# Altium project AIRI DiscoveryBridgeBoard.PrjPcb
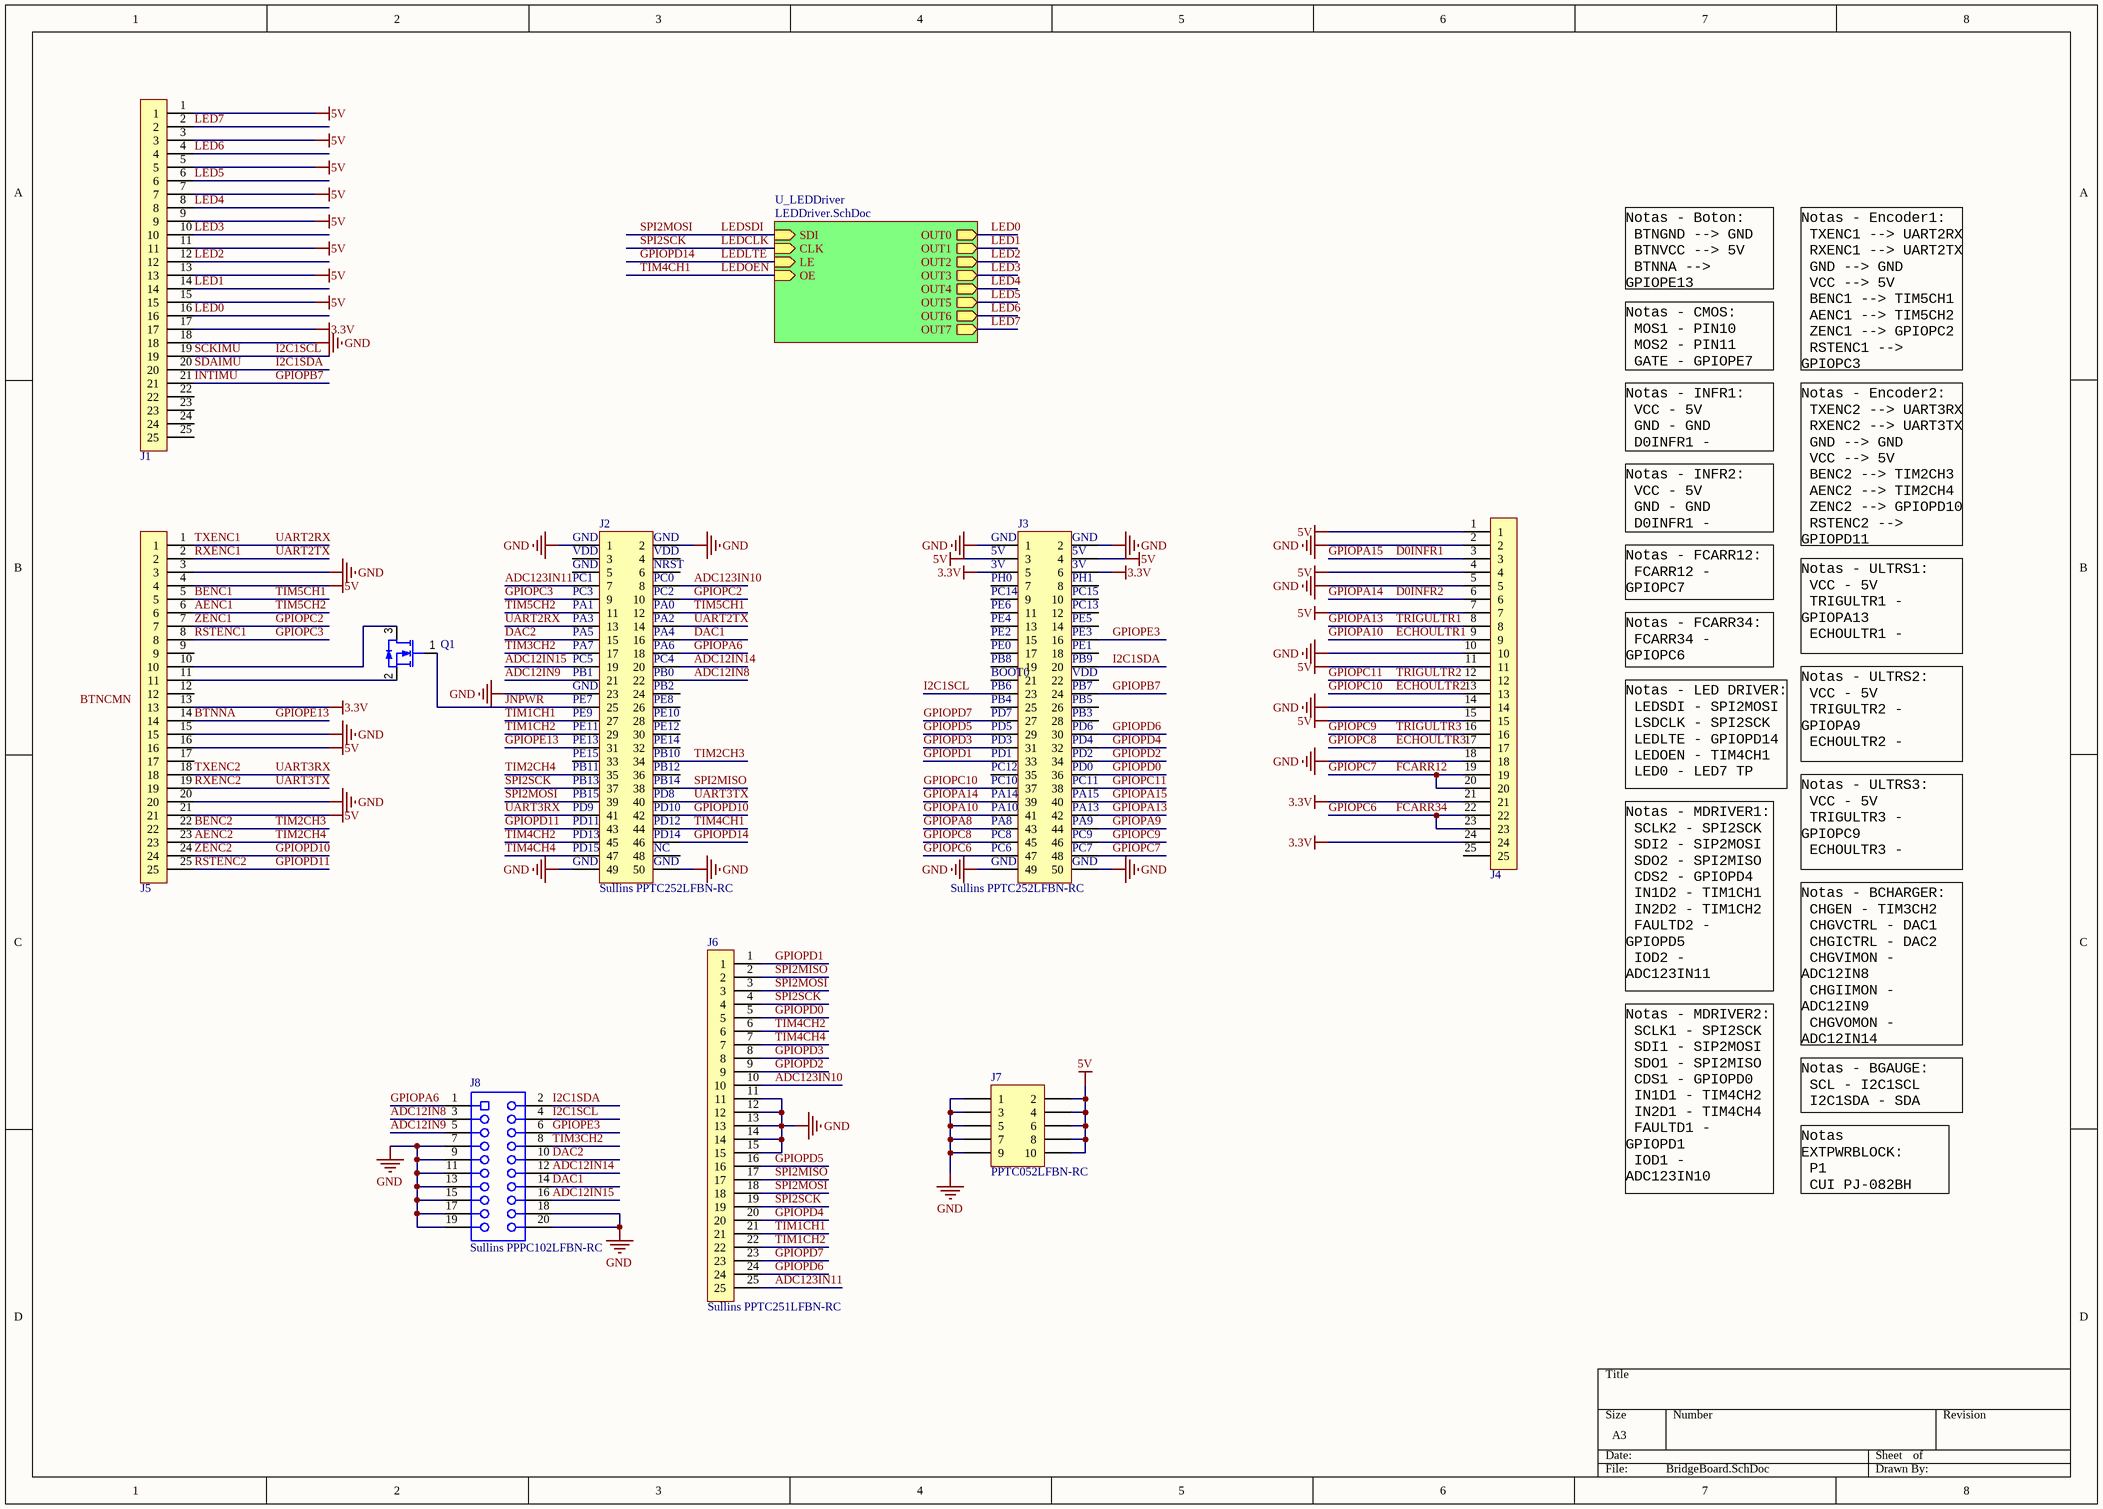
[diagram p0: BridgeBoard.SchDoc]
2 sheets, 12 parts. Net scope: hierarchical (ports join the sheet entries above them; power ports are global).
Sheets:
  BridgeBoard.SchDoc
    U_LEDDriver = LEDDriver.SchDoc

## Sheet BridgeBoard.SchDoc
size A3; DocumentNumber: 1; SheetNumber: 1; SheetTotal: 9

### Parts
J1  Sullins PREC025SAAN-RC  [PCB-ss9uik38su1ryg1jck95-1]  (value not drawn)
J2  Sullins PPTC252LFBN-RC  [SMTC-SSW-125-01-X-D]
J3  Sullins PPTC252LFBN-RC  [SMTC-SSW-125-01-X-D]
J4  Sullins PREC025SAAN-RC  [PCB-ss9uik38su1ryg1jck95-1]  (value not drawn)
J5  Sullins PREC025SAAN-RC  [PCB-ss9uik38su1ryg1jck95-1]  (value not drawn)
J6  Sullins PPTC251LFBN-RC  [PCBComponent_1]
J7  PPTC052LFBN-RC  [PCB-uuwva20n0c04talkzipv-1]
J8  Sullins PPPC102LFBN-RC  [SLIN-PPPC102LFBN-RC_V]
Q1  ON Semiconductor NTR5103NT1G  [PCB-4trtqjanqmpdw865ivvf-1]  (value not drawn)

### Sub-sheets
U_LEDDriver = LEDDriver.SchDoc: OUT0 (out), OUT1 (out), OUT2 (out), OUT3 (out), OUT4 (out), OUT5 (out), OUT6 (out), OUT7 (out), SDI (in), CLK (in), LE (in), OE (in)

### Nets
3.3V: J1.17 J3.5 J3.6 J4.21 J4.24 J5.13
5V: J1.1 J1.3 J1.5 J1.7 J1.9 J1.11 J1.13 J1.15 J3.3 J3.4 J4.1 J4.4 J4.7 J4.11 J4.15 J5.4 J5.16 J5.21 J7.2 J7.4 J7.6 J7.8 J7.10
GND: J1.18 J2.1 J2.2 J2.23 J2.49 J2.50 J3.1 J3.2 J3.49 J3.50 J4.2 J4.5 J4.10 J4.14 J4.18 J5.3 J5.15 J5.20 J6.11 J6.12 J6.13 J6.14 J6.15 J7.1 J7.3 J7.5 J7.7 J7.9 J8.7 J8.9 J8.11 J8.13 J8.15 J8.17 J8.18 J8.19 J8.20
ADC12IN8: J2.22 J8.3
ADC12IN9: J2.21 J8.5
ADC12IN14: J2.20 J8.12
ADC12IN15: J2.19 J8.16
ADC123IN10: J2.8 J6.10
ADC123IN11: J2.7 J6.25
AENC1: J2.11 J5.6  [also labelled TIM5CH2]
AENC2: J2.35 J5.23  [also labelled TIM2CH4]
BENC1: J2.12 J5.5  [also labelled TIM5CH1]
BENC2: J2.34 J5.22  [also labelled TIM2CH3]
BTNNA: J2.31 J5.14  [also labelled GPIOPE13]
D0INFR1: J3.40 J4.3  [also labelled GPIOPA15]
D0INFR2: J3.39 J4.6  [also labelled GPIOPA14]
DAC1: J2.16 J8.14
DAC2: J2.15 J8.10
ECHOULTR1: J3.41 J4.9  [also labelled GPIOPA10]
ECHOULTR2: J3.37 J4.13  [also labelled GPIOPC10]
ECHOULTR3: J3.45 J4.17  [also labelled GPIOPC8]
FCARR12: J3.48 J4.19 J4.20  [also labelled GPIOPC7]
FCARR34: J3.47 J4.22 J4.23  [also labelled GPIOPC6]
GPIOPA6: J2.18 J8.1
GPIOPA8: J3.43
GPIOPA9: J3.44
GPIOPA13: J3.42 J4.8  [also labelled TRIGULTR1]
GPIOPB7: J1.21 J3.24  [also labelled INTIMU]
GPIOPC2: J2.10 J5.7  [also labelled ZENC1]
GPIOPC3: J2.9 J5.8  [also labelled RSTENC1]
GPIOPC9: J3.46 J4.16  [also labelled TRIGULTR3]
GPIOPC11: J3.38 J4.12  [also labelled TRIGULTR2]
GPIOPD0: J3.36 J6.5
GPIOPD1: J3.33 J6.1
GPIOPD2: J3.34 J6.9
GPIOPD3: J3.31 J6.8
GPIOPD4: J3.32 J6.20
GPIOPD5: J3.29 J6.16
GPIOPD6: J3.30 J6.24
GPIOPD7: J3.27 J6.23
GPIOPD10: J2.42 J5.24  [also labelled ZENC2]
GPIOPD11: J2.43 J5.25  [also labelled RSTENC2]
GPIOPD14: J2.46 ; sheet U_LEDDriver/LE  [also labelled LEDLTE]
GPIOPE3: J3.16 J8.6
I2C1SCL: J1.19 J3.23 J8.4  [also labelled SCKIMU]
I2C1SDA: J1.20 J3.20 J8.2  [also labelled SDAIMU]
JNPWR: J2.25 Q1.1(G)
LED0: J1.16 ; sheet U_LEDDriver/OUT0
LED1: J1.14 ; sheet U_LEDDriver/OUT1
LED2: J1.12 ; sheet U_LEDDriver/OUT2
LED3: J1.10 ; sheet U_LEDDriver/OUT3
LED4: J1.8 ; sheet U_LEDDriver/OUT4
LED5: J1.6 ; sheet U_LEDDriver/OUT5
LED6: J1.4 ; sheet U_LEDDriver/OUT6
LED7: J1.2 ; sheet U_LEDDriver/OUT7
LEDCLK: J2.37 J6.4 J6.19 ; sheet U_LEDDriver/CLK  [also labelled SPI2SCK]
LEDOEN: J2.44 ; sheet U_LEDDriver/OE  [also labelled TIM4CH1]
LEDSDI: J2.39 J6.3 J6.18 ; sheet U_LEDDriver/SDI  [also labelled SPI2MOSI]
RXENC1: J2.14 J5.2  [also labelled UART2TX]
RXENC2: J2.40 J5.19  [also labelled UART3TX]
SPI2MISO: J2.38 J6.2 J6.17
TIM1CH1: J2.27 J6.21
TIM1CH2: J2.29 J6.22
TIM3CH2: J2.17 J8.8
TIM4CH2: J2.45 J6.6
TIM4CH4: J2.47 J6.7
TXENC1: J2.13 J5.1  [also labelled UART2RX]
TXENC2: J2.41 J5.18  [also labelled UART3RX]
NetJ5_10: J5.10 Q1.3(D)
NetJ5_11: J5.11 Q1.2(S)

Not connected (* = marked no-connect by the designer): J1 22 23 24 25; J2 3 4 5 6 24 26 28 30 32 33 36 48; J3 7 8 9 10 11 12 13 14 15 17 18 19 21 22 25 26 28 35; J4 25; J5 9 12 17

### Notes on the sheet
- Notas - Boton:
  BTNGND --> GND
  BTNVCC --> 5V
  BTNNA --> GPIOPE13
  BTNCMN --> 3.3V
- Notas - CMOS:
  MOS1 - PIN10
  MOS2 - PIN11
  GATE - GPIOPE7
- Notas - Encoder1:
  TXENC1 --> UART2RX
  RXENC1 --> UART2TX
  GND --> GND
  VCC --> 5V
  BENC1 --> TIM5CH1
  AENC1 --> TIM5CH2
  ZENC1 --> GPIOPC2
  RSTENC1 --> GPIOPC3
- Notas - INFR1:
  VCC - 5V
  GND - GND
  D0INFR1 - GPIOPA15
- (near J2) PC1
- (near J2) GND
- (near J2) VDD
- (near J2) NRST
- (near J2) PC0
- (near J3) GND
- (near J3) PH0
- (near J3) 5V
- (near J3) 3V
- (near J3) PH1
- Notas - INFR2:
  VCC - 5V
  GND - GND
  D0INFR1 - GPIOPA14
- Notas - Encoder2:
  TXENC2 --> UART3RX
  RXENC2 --> UART3TX
  GND --> GND
  VCC --> 5V
  BENC2 --> TIM2CH3
  AENC2 --> TIM2CH4
  ZENC2 --> GPIOPD10
  RSTENC2 --> GPIOPD11
- (near J2) PA7
- (near J2) PA5
- (near J2) PA3
- (near J2) PA1
- (near J2) PC3
- (near J2) PC2
- (near J2) PA0
- (near J2) PA2
- (near J2) PA4
- (near J2) PA6
- (near J3) PC14
- (near J3) PE6
- (near J3) PE4
- (near J3) PE2
- (near J3) PE0
- (near J3) PE1
- (near J3) PE3
- (near J3) PE5
- (near J3) PC13
- (near J3) PC15
- Notas - FCARR12:
  FCARR12 - GPIOPC7
  GND - GND
- Notas - ULTRS1:
  VCC - 5V
  TRIGULTR1 - GPIOPA13
  ECHOULTR1 - GPIOPA10
  GND - GND
- (near J2) PE9
- (near J2) PE7
- (near J2) PB1
- (near J2) PC5
- (near J2) PC4
- (near J2) PB0
- (near J2) PB2
- (near J2) PE8
- (near J2) PE10
- (near J3) PB8
- (near J3) BOOT0
- (near J3) PB6
- (near J3) PB4
- (near J3) PD7
- (near J3) PB3
- (near J3) PB5
- (near J3) PB7
- (near J3) VDD
- (near J3) PB9
- Notas - FCARR34:
  FCARR34 - GPIOPC6
  GND - GND
- (near J2) PB13
- (near J2) PB11
- (near J2) PE15
- (near J2) PE13
- (near J2) PE11
- (near J2) PE12
- (near J2) PE14
- (near J2) PB10
- (near J2) PB12
- (near J2) PB14
- (near J3) PD5
- (near J3) PD3
- (near J3) PD1
- (near J3) PC12
- (near J3) PC10
- (near J3) PC11
- (near J3) PD0
- (near J3) PD2
- (near J3) PD4
- (near J3) PD6
- Notas - LED DRIVER:
  LEDSDI - SPI2MOSI
  LSDCLK - SPI2SCK
  LEDLTE - GPIOPD14
  LEDOEN - TIM4CH1
  LED0 - LED7 TP
- Notas - ULTRS2:
  VCC - 5V
  TRIGULTR2 - GPIOPA9
  ECHOULTR2 - GPIOPA8
  GND - GND
- (near J2) PD15
- (near J2) PD13
- (near J2) PD11
- (near J2) PD9
- (near J2) PB15
- (near J2) PD8
- (near J2) PD10
- (near J2) PD12
- (near J2) PD14
- (near J2) NC
- (near J3) PA14
- (near J3) PA10
- (near J3) PA8
- (near J3) PC8
- (near J3) PC6
- (near J3) PC7
- (near J3) PC9
- (near J3) PA9
- (near J3) PA13
- (near J3) PA15
- Notas - ULTRS3:
  VCC - 5V
  TRIGULTR3 - GPIOPC9
  ECHOULTR3 - GPIOPC8
  GND - GND
- Notas - MDRIVER1:
  SCLK2 - SPI2SCK
  SDI2 - SIP2MOSI
  SDO2 - SPI2MISO
  CDS2 - GPIOPD4
  IN1D2 - TIM1CH1
  IN2D2 - TIM1CH2
  FAULTD2 - GPIOPD5
  IOD2 - ADC123IN11
  SLPD2 - GPIOPD6
  DISD2 - GPIOPD7
- Notas - BCHARGER:
  CHGEN - TIM3CH2
  CHGVCTRL - DAC1
  CHGICTRL - DAC2
  CHGVIMON - ADC12IN8
  CHGIIMON - ADC12IN9
  CHGVOMON - ADC12IN14
  CHGIOMON - ADC12IN15
  CHGFAULT - GPIOPA6
- Notas - BGAUGE:
  SCL - I2C1SCL
  I2C1SDA - SDA
- Notas - MDRIVER2:
  SCLK1 - SPI2SCK
  SDI1 - SIP2MOSI
  SDO1 - SPI2MISO
  CDS1 - GPIOPD0
  IN1D1 - TIM4CH2
  IN2D1 - TIM4CH4
  FAULTD1 - GPIOPD1
  IOD1 - ADC123IN10
  SLPD1 - GPIOPD2
  DISD1 - GPIOPD3
- Notas EXTPWRBLOCK:
  P1
  CUI PJ-082BH
- Labels drawn without touching a wire or pin: BTNCMN

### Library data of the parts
J1 J4 J5 = CMP-10abd8f28bd1cf6c-1: Conn Header Vert 25POS 2.54MM
J2 J3 = CMP-d2a41baad4c10d63-2: 50 Position Header Connector 0.100" (2.54mm) Through Hole Tin; Number of Positions: 50; Lead-Free Status: Lead Free
J6 = CMP-bb84728abc226443-1: Conn Hdr 25POS 0.1 Tin Pcb; Lead-Free Status: Lead Free; Number of Positions: 25; Pin Pitch: 2.54 mm
J7 = CMP-a5ef6ce1a39b7a28-1: Female, 10C, Straight, .100"CC; 3.20mm Tail, No Mounting; PBT, Phos. Bronze, 105 C; Manufacturer Part Number: PPPC052LFBN-RC; Pin Pitch: 2.54 mm; Number of Positions: 10
J8 = CMP-dcfd15f3db31033a-2: Female Header, Pitch 2.54 mm, 2 x 10 Position, Height 8.75 mm, Tail Length 3.2 mm, -40 to 105 degC, RoHS, Bulk; Pin Pitch: 2.54 mm; Number of Positions: 20; Lead-Free Status: Lead Free
Q1 = CMP-02f4c92c4c09dd33-6: Small Signal MOSFET 60V 310mA 2.5mOhm Single N-Channel SOT-23 Small Signal MOSFET

## Sheet LEDDriver.SchDoc
size A; DocumentNumber: 8; SheetNumber: 8; SheetTotal: 9
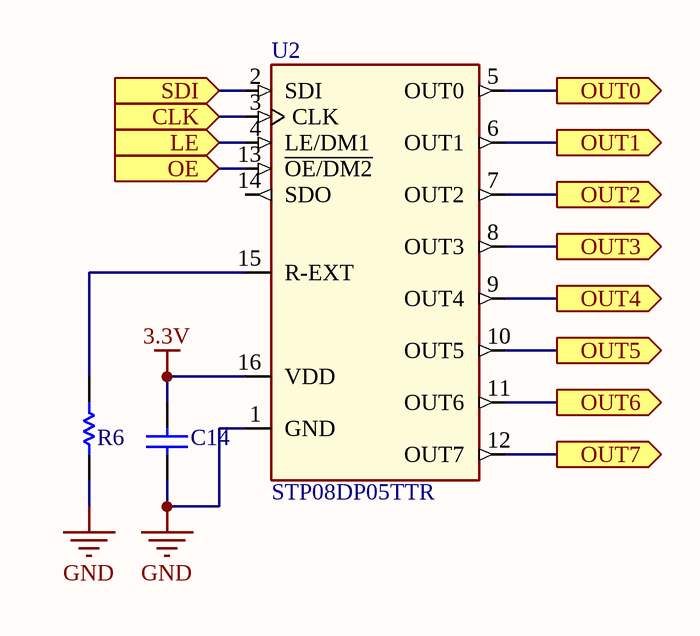
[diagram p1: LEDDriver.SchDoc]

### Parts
C14  Murata GCD21BR71H104KA01L  [PCB-ssva2zk340p4bh5zvq6f-1]  (value not drawn)
R6  Yageo RC0805FR-07820RL  [PCB-tlec0rbgb5i2w1be04n0-1]  (value not drawn)
U2  STP08DP05TTR  [PCB-im79j1cdrkmt1twk6fi6-1]

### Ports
CLK (in), LE (in), OE (in), OUT0 (out), OUT1 (out), OUT2 (out), OUT3 (out), OUT4 (out), OUT5 (out), OUT6 (out), OUT7 (out), SDI (in)

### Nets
3.3V: C14.2 U2.16(VDD)
GND: C14.1 R6.2 U2.1(GND)
GPIOPD14: U2.4(LE/DM1) ; port LE
LED0: U2.5(OUT0) ; port OUT0
LED1: U2.6(OUT1) ; port OUT1
LED2: U2.7(OUT2) ; port OUT2
LED3: U2.8(OUT3) ; port OUT3
LED4: U2.9(OUT4) ; port OUT4
LED5: U2.10(OUT5) ; port OUT5
LED6: U2.11(OUT6) ; port OUT6
LED7: U2.12(OUT7) ; port OUT7
LEDCLK: U2.3(CLK) ; port CLK
LEDOEN: U2.13(~{OE/DM2}) ; port OE
LEDSDI: U2.2(SDI) ; port SDI
NetR6_1: R6.1 U2.15(R-EXT)

Not connected (* = marked no-connect by the designer): U2 14(SDO)

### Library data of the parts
C14 = CMP-5b5d9311dba3849a-1: Cap Ceramic 0.1uF 50V X7R 10% Pad SMD 0805 125C Automotive T/R; Capacitance: 100 nF; Voltage Rating (DC): 50.0 V
R6 = CMP-d46c1f1e7e700bab-2: Surface Mount Thick Film Resistor, RC Series, 820 ohm, 125 mW, - 1%, 150 V, 0805 [2012 Metric]; Lead-Free Status: Lead Free; Case/Package (SI): 2012; Power Rating: 125 mW; Resistance: 820 ?; Voltage Rating (DC): 150 V
U2 = CMP-0535cc0201d5daf2-4: STP08DP05 Series 100mA 30 MHz Low Voltage Low Current Power 8-bit Shift Register; Input Voltage (DC): 3.00 V to 5.50 V; Lead-Free Status: Lead Free; Output Voltage: 20.0 V; Number of Outputs: 8

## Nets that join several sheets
3.3V: BridgeBoard (6 pins), LEDDriver (C14.2 U2.16)
GND: BridgeBoard (37 pins), LEDDriver (C14.1 R6.2 U2.1)
GPIOPD14: BridgeBoard (J2.46), LEDDriver (U2.4)
LED0: BridgeBoard (J1.16), LEDDriver (U2.5)
LED1: BridgeBoard (J1.14), LEDDriver (U2.6)
LED2: BridgeBoard (J1.12), LEDDriver (U2.7)
LED3: BridgeBoard (J1.10), LEDDriver (U2.8)
LED4: BridgeBoard (J1.8), LEDDriver (U2.9)
LED5: BridgeBoard (J1.6), LEDDriver (U2.10)
LED6: BridgeBoard (J1.4), LEDDriver (U2.11)
LED7: BridgeBoard (J1.2), LEDDriver (U2.12)
LEDCLK: BridgeBoard (J2.37 J6.4 J6.19), LEDDriver (U2.3)
LEDOEN: BridgeBoard (J2.44), LEDDriver (U2.13)
LEDSDI: BridgeBoard (J2.39 J6.3 J6.18), LEDDriver (U2.2)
